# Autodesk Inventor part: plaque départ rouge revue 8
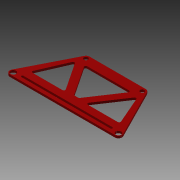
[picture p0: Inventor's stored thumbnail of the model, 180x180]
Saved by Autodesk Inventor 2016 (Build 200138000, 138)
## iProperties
Created: 2015-08
Part Number: plaque départ rouge revue 8
Material: Générique
Document SubType Name: Modeling
Designer: Dominique
Density: 1 g/cm^3
Appearance: Rouge
Author: Dominique
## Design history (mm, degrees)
sketch "Esquisse1" dims "d28" = 60
  geometry: L1 (0, -5)-(110, -5); L2 (0, 5)-(110, 5); L3 (0, 0)-(102, 0); L4 (0, 72)-(24.95, 73.58); L5 (39.034, 94.236)-(24.95, 73.58); L6 (0, 0)-(24.95, 73.58); L7 (0, 0)-(77.695, 0); L8 (0, 0)-(34.388, 69.671); L9 (39.034, 94.236)-(34.388, 69.671); L10 (-150, 5)-(0, 5); L11 (0, -5)-(-150, -5); L12 (0, 0)-(-101.627, 42.095); L13 (-150, 0)-(0, 0); L14 (99.713, 46.715)-(-1.913, 4.619); L15 (103.54, 37.476)-(1.913, -4.619); L16 (0, 0)-(0, 102); L17 (0, 102)-(0, 72); L18 (-29.83, 68.812)-(0, 0); L19 (-150, 0)-(-120.166, 68.811); L20 (-150, 0)-(-75, 0); L21 (-120.166, 68.811)-(-29.83, 68.812); C1 r 5 at (24.95, 73.58); C2 r 5 at (34.388, 69.671); C3 r 5 at (-29.83, 68.812); C4 r 5 at (-11.182, 74.162); C5 r 5 at (-120.166, 68.811); A1 r 5 centre (0, 0) between (0, -5) and (0, 5); A2 r 5 centre (110, 0) between (110, -5) and (110, 5); A3 r 5 centre (-150, 0) between (-150, 5) and (-150, -5); A4 r 5 centre (-101.627, 42.095) between (-99.609, 46.67) and (-103.435, 37.433); A5 r 5 centre (101.627, 42.095) between (99.713, 46.715) and (103.54, 37.476); A6 r 110 centre (0, 0) between (-99.609, 46.67) and (-103.435, 37.433); A7 r 150 centre (0, 0) between (-149.917, 5) and (-149.917, -5); A8 r 110 centre (0, 0) between (109.886, -5) and (109.886, 5); A9 r 110 centre (0, 0) between (103.435, 37.432) and (99.608, 46.671); A10 r 30 centre (0, 102) between (0, 72) and (-11.182, 74.162); A11 r 75 centre (0, 0) between (-29.83, 68.812) and (-11.182, 74.162); 1 further point
  constraints: 42 end point, 27 point on circle, 16 centre point, 11 tangent, 8 coincident, 6 point on line, 4 horizontal, 1 collinear, 1 equal length, 1 vertical, 3 other
  dimensions: "d0" = 10 diameter of A1; "d1" = 10 diameter of A2; "d2" = 110 distance of A2.centre point (0, 0); "d13" = 10 diameter of C1; "d14" = 71.2689 deg angle of L1 L6; "d18" = 77.69525 distance of L3.start L6.end; "d19" = 77.69525 distance of L3.start L8.end (= d18); "d20" = 10 diameter of C2; "d21" = 10 diameter of A3; "d22" = 150 distance of point (0, 0) L13.start; "d23" = 10 diameter of A4; "d25" = 22.5 deg angle of L10 L12; "d26" = 10 diameter of A5; "d27" = 102 distance of L13.end L16.end; "d29" = 150 diameter of A11; "d30" = 10 diameter of C3; "d31" = 10 diameter of C4; "d32" = 66.5633 deg angle of L13 L18; "d33" = 66.56 deg angle of L20 L19; "d34" = 10 diameter of C5; "d35" = 75 distance of L18.start L3.start; "d36" = 75 distance of L13.start L19.end (= d35)
sketch "Esquisse2"
  geometry: L1 (-34.83, 73.82)-(-75, 73.819) reference; L2 (-75, -4.993)-(0, -4.993) reference; L3 (-75, 3.007)-(-11.5, 3.007); L4 (-10, 1.507)-(-10, 1.507); L5 (-11.5, 0.007)-(-75, 0.007); L6 (-58.613, 16.278)-(-32.731, 55.178); L7 (-29.231, 54.866)-(-12.367, 15.966); L8 (-14.202, 13.17)-(-56.948, 13.17); L9 (-75, 60.227)-(-45.115, 60.227); L10 (-43.45, 57.119)-(-70.905, 15.857); L11 (-72.57, 14.965)-(-75, 14.965); L12 (0, 0.007)-(148.726, 0.007); L13 (-30.369, 71.078)-(4.461, 2.265); L14 (-77.43, 14.965)-(-75, 14.965); L15 (-140, 1.507)-(-140, 1.507); L16 (-119.631, 71.078)-(-154.461, 2.265); L17 (-120.769, 54.866)-(-137.633, 15.966); L18 (-115.17, 73.82)-(-75, 73.819); L19 (-75, -4.993)-(-150, -4.993); L20 (-75, 3.007)-(-138.5, 3.007); L21 (-138.5, 0.007)-(-75, 0.007); L22 (-135.798, 13.17)-(-93.052, 13.17); L23 (-106.55, 57.119)-(-79.095, 15.857); L24 (-91.387, 16.278)-(-117.269, 55.178); L25 (-75, 60.227)-(-104.885, 60.227); C1 r 3 at (0, 0.007); C2 r 3 at (-34.83, 68.82); C3 r 3 at (-150, 0.007); C4 r 3 at (-115.17, 68.82); A1 r 5 centre (0, 0.007) between (0, -4.993) and (4.461, 2.265); A2 r 1.5 centre (-11.5, 1.507) between (-10, 1.507) and (-11.5, 3.007); A3 r 1.5 centre (-11.5, 1.507) between (-11.5, 0.007) and (-10, 1.507); A4 r 2 centre (-72.57, 16.965) between (-72.57, 14.965) and (-70.905, 15.857); A5 r 2 centre (-45.115, 58.227) between (-43.45, 57.119) and (-45.115, 60.227); A6 r 2 centre (-31.066, 54.07) between (-29.231, 54.866) and (-32.731, 55.178); A7 r 2 centre (-56.948, 15.17) between (-58.613, 16.278) and (-56.948, 13.17); A8 r 2 centre (-14.202, 15.17) between (-14.202, 13.17) and (-12.367, 15.966); A9 r 5 centre (-34.83, 68.82) between (-30.369, 71.078) and (-34.83, 73.82); A10 r 2 centre (-93.052, 15.17) between (-93.052, 13.17) and (-91.387, 16.278); A11 r 2 centre (-77.43, 16.965) between (-79.095, 15.857) and (-77.43, 14.965); A12 r 5 centre (-150, 0.007) between (-154.461, 2.265) and (-150, -4.993); A13 r 1.5 centre (-138.5, 1.507) between (-140, 1.507) and (-138.5, 0.007); A14 r 1.5 centre (-138.5, 1.507) between (-138.5, 3.007) and (-140, 1.507); A15 r 2 centre (-135.798, 15.17) between (-137.633, 15.966) and (-135.798, 13.17); A16 r 2 centre (-104.885, 58.227) between (-104.885, 60.227) and (-106.55, 57.119); A17 r 2 centre (-118.934, 54.07) between (-117.269, 55.178) and (-120.769, 54.866); A18 r 5 centre (-115.17, 68.82) between (-115.17, 73.82) and (-119.631, 71.078); 12 further points
  constraints: 52 end point, 38 point on circle, 22 centre point, 20 point on line, 17 tangent, 5 equal radius, 4 coincident, 4 horizontal, 3 parallel, 1 perpendicular, 1 other
  dimensions: "d42" = 10 diameter of A1; "d48" = 6 diameter of C1; "d51" = 3 distance of point (-10, 3.007) point (-10, 0.007); "d53" = 10 distance from line of L4 point (0, 0); "d56" = 3 distance between parallel lines of L5 L3 (derived); "d62" = 56.3616 deg angle of L8 L6 (= d61); "d64" = 63.23263 distance from line of point (-30.693, 58.24) L2 (= d63); "d65" = 10 distance between parallel lines of L6 L10; "d75" = 6 diameter of C2
extrude "Extrusion1" new body sketch "Esquisse2" distance "d68" = 3; taper "d69" = 0 deg
sketch "Esquisse4"
  geometry: C1 r 3 at (-150, 0.007) reference; C2 r 3 at (0, 0.007) reference; C3 r 4 at (-150, 0.007); C4 r 4 at (0, 0.007); 1 further point
  constraints: 2 centre point, 2 coincident
  dimensions: "d76" = 8 diameter of C3; "d77" = 8 diameter of C4
extrude "Extrusion3" cut sketch "Esquisse4" distance "d78" = 10; taper "d79" = 0 deg
node "Solide1"
other parameters: "d61" = 56.3616 deg, "d63" = 63.23263
